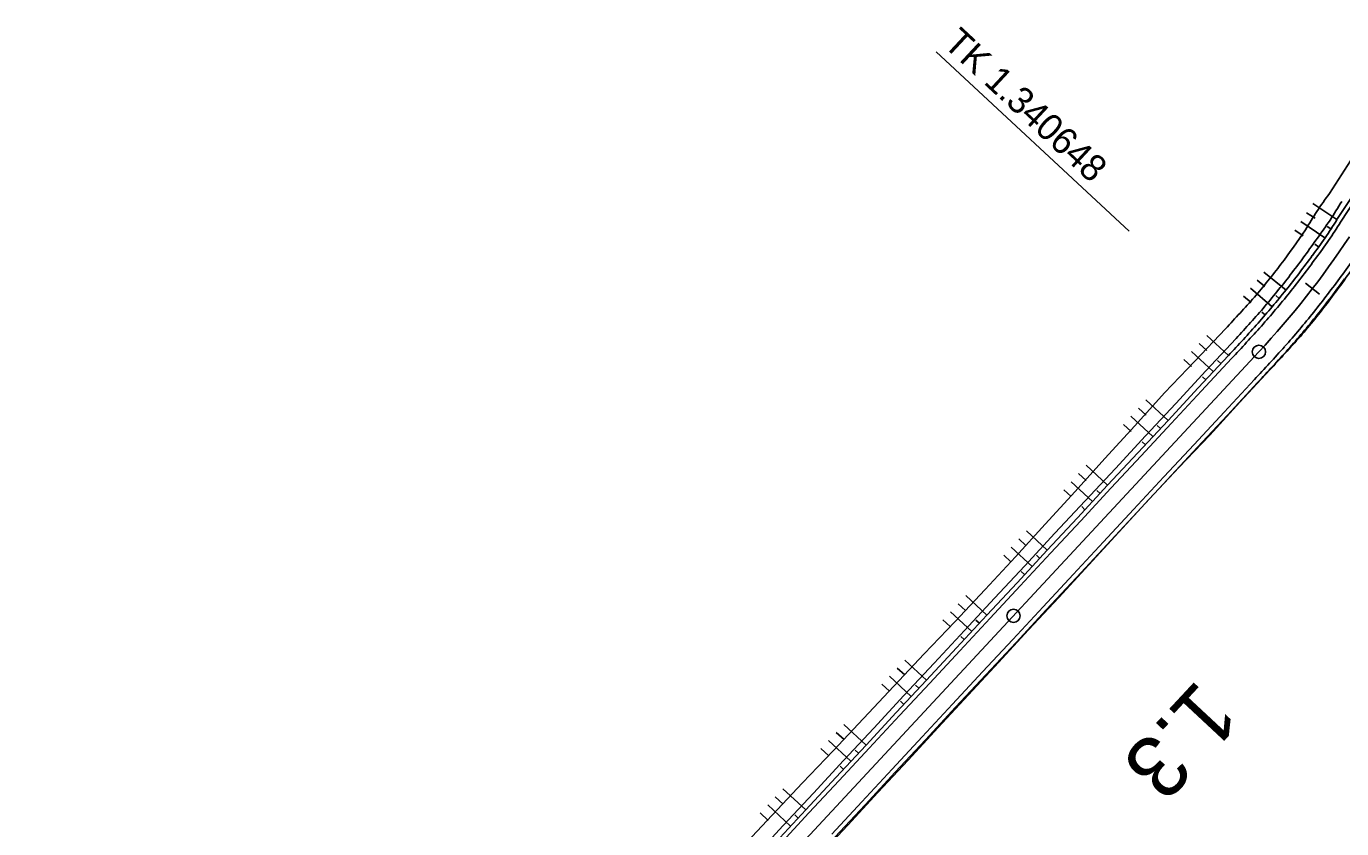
# Model space of a CAD drawing. Extents: x -481645 to -478728, y -1113199 to -1110710.
# Drawn here: x -479136.3 to -478987.9, y -1110857.1 to -1110766.6 of the extents above; entities that cross this region are included whole.
import ezdxf

# ---------------------------------------------------------------- set-up
doc = ezdxf.new("R2010")
doc.units = 0
for name, color, linetype in [('CP14_HATCH_SLOPE_L', 7, 'Continuous'), ('CP1_HECTOMETRY', 7, 'Continuous'), ('O6_HATCH_SLOPE_L', 7, 'Continuous'), ('O6_HATCH_SLOPE_R', 7, 'Continuous'), ('O6_HECTOMETRY', 7, 'Continuous'), ('O6_HLBODY', 7, 'Continuous'), ('O6_HRANA_TELESO', 7, 'Continuous'), ('O6_OSA', 7, 'Continuous'), ('O6_VOZOVKA', 7, 'Continuous'), ('O6_ZPEVKRAJ', 7, 'Continuous')]:
    doc.layers.add(name, color=color, linetype=linetype)

msp = doc.modelspace()

# ---------------------------------------------------------------- linework, layer by layer
at = {"layer": 'CP14_HATCH_SLOPE_L'}
for p, q in [((-478988.66, -1110796.55), (-478988.64, -1110796.57)), ((-478988.61, -1110796.59), (-478988.61, -1110796.59)), ((-478992.65, -1110801.54), (-478992.59, -1110801.59)), ((-478994.33, -1110803.47), (-478994.29, -1110803.5)), ((-478993.49, -1110802.51), (-478993.46, -1110802.53)), ((-478993.43, -1110802.55), (-478993.43, -1110802.55)), ((-478995.19, -1110804.41), (-478995.18, -1110804.43)), ((-478995.16, -1110804.44), (-478995.16, -1110804.44)), ((-478999.46, -1110809), (-478999.43, -1110809.02)), ((-479001.16, -1110810.83), (-479001.12, -1110810.87)), ((-479000.31, -1110809.92), (-479000.29, -1110809.93)), ((-479000.28, -1110809.95), (-479000.28, -1110809.95)), ((-479002.01, -1110811.75), (-479001.98, -1110811.77)), ((-479001.96, -1110811.79), (-479001.96, -1110811.79)), ((-479006.27, -1110816.32), (-479006.24, -1110816.35)), ((-479007.97, -1110818.15), (-479007.95, -1110818.17)), ((-479007.12, -1110817.24), (-479007.11, -1110817.25)), ((-479007.1, -1110817.26), (-479007.1, -1110817.26)), ((-479008.82, -1110819.07), (-479008.82, -1110819.07)), ((-479008.81, -1110819.08), (-479008.81, -1110819.08)), ((-479013.08, -1110823.65), (-479013.05, -1110823.67)), ((-479014.78, -1110825.48), (-479014.75, -1110825.51)), ((-479013.93, -1110824.56), (-479013.91, -1110824.57)), ((-479013.9, -1110824.59), (-479013.9, -1110824.59)), ((-479015.63, -1110826.39), (-479015.61, -1110826.41)), ((-479015.6, -1110826.43), (-479015.6, -1110826.43)), ((-479019.89, -1110830.97), (-479019.83, -1110831.02)), ((-479021.59, -1110832.8), (-479021.53, -1110832.86)), ((-479020.74, -1110831.89), (-479020.71, -1110831.91)), ((-479020.68, -1110831.94), (-479020.68, -1110831.94)), ((-479022.44, -1110833.72), (-479022.41, -1110833.75)), ((-479022.38, -1110833.77), (-479022.38, -1110833.77)), ((-479027.55, -1110839.21), (-479027.51, -1110839.24)), ((-479027.48, -1110839.27), (-479027.48, -1110839.27)), ((-479026.7, -1110838.29), (-479026.62, -1110838.36)), ((-479028.4, -1110840.12), (-479028.33, -1110840.19)), ((-479029.25, -1110841.04), (-479029.21, -1110841.07)), ((-479029.17, -1110841.11), (-479029.17, -1110841.11)), ((-479034.36, -1110846.53), (-479034.32, -1110846.57)), ((-479034.28, -1110846.61), (-479034.28, -1110846.61)), ((-479033.51, -1110845.62), (-479033.42, -1110845.69)), ((-479035.21, -1110847.45), (-479035.12, -1110847.52)), ((-479036.06, -1110848.36), (-479036.02, -1110848.4)), ((-479035.98, -1110848.44), (-479035.98, -1110848.44)), ((-479041.17, -1110853.85), (-479041.12, -1110853.9)), ((-479041.08, -1110853.94), (-479041.08, -1110853.94)), ((-479040.32, -1110852.94), (-479040.23, -1110853.02)), ((-479042.02, -1110854.77), (-479041.92, -1110854.85)), ((-479042.87, -1110855.69), (-479042.82, -1110855.73)), ((-479042.78, -1110855.77), (-479042.78, -1110855.77))]:
    msp.add_line(p, q, dxfattribs=at)
at = {"layer": 'CP1_HECTOMETRY'}
msp.add_line((-479231.87, -1111055.62), (-478997.26, -1110803.33), dxfattribs=at)
msp.add_arc((-479070.49, -1110735.23), 100, 317.0793, 326.545, dxfattribs=at)
at = {"layer": 'O6_HATCH_SLOPE_L'}
msp.add_circle((-479024.94, -1110833.1), 0.75, dxfattribs=at)
at = {"layer": 'O6_HATCH_SLOPE_R'}
for p, q in [((-478988.47, -1110788.42), (-478991.2, -1110786.61)), ((-478989.84, -1110790.47), (-478992.53, -1110788.62)), ((-478990.93, -1110788.27), (-478991.88, -1110787.64)), ((-478992.27, -1110790.25), (-478993.2, -1110789.6)), ((-478989.16, -1110789.46), (-478989.57, -1110789.18)), ((-478990.54, -1110791.47), (-478990.94, -1110791.19)), ((-478994.2, -1110796.36), (-478996.72, -1110794.34)), ((-478995.76, -1110798.24), (-478998.23, -1110796.16)), ((-478996.61, -1110795.96), (-478997.47, -1110795.26)), ((-478998.15, -1110797.78), (-478999, -1110797.05)), ((-478994.97, -1110797.3), (-478995.36, -1110796.99)), ((-478996.55, -1110799.17), (-478996.93, -1110798.84)), ((-479000.7, -1110803.73), (-479003.13, -1110801.48)), ((-479002.41, -1110805.56), (-479004.86, -1110803.28)), ((-479003.14, -1110803.17), (-479003.99, -1110802.38)), ((-479004.86, -1110804.99), (-479005.72, -1110804.19)), ((-479001.55, -1110804.65), (-479001.92, -1110804.3)), ((-479003.26, -1110806.48), (-479003.63, -1110806.14)), ((-479007.51, -1110811.06), (-479010, -1110808.74)), ((-479009.22, -1110812.89), (-479011.69, -1110810.59)), ((-479009.98, -1110810.47), (-479010.85, -1110809.67)), ((-479011.67, -1110812.31), (-479012.53, -1110811.51)), ((-479008.36, -1110811.97), (-479008.74, -1110811.63)), ((-479010.07, -1110813.8), (-479010.44, -1110813.46)), ((-479014.32, -1110818.38), (-479016.75, -1110816.12)), ((-479016.03, -1110820.21), (-479018.43, -1110817.97)), ((-479016.76, -1110817.82), (-479017.59, -1110817.05)), ((-479018.45, -1110819.66), (-479019.28, -1110818.89)), ((-479015.17, -1110819.29), (-479015.55, -1110818.95)), ((-479016.88, -1110821.13), (-479017.25, -1110820.78)), ((-479023.54, -1110825.17), (-479024.34, -1110824.43)), ((-479021.13, -1110825.7), (-479023.49, -1110823.51)), ((-479022.84, -1110827.53), (-479025.19, -1110825.35)), ((-479025.24, -1110827.01), (-479026.03, -1110826.27)), ((-479021.98, -1110826.62), (-479022.36, -1110826.27)), ((-479023.69, -1110828.45), (-479024.06, -1110828.1)), ((-479030.36, -1110832.48), (-479031.17, -1110831.73)), ((-479027.94, -1110833.02), (-479030.31, -1110830.82)), ((-479029.65, -1110834.86), (-479032.03, -1110832.64)), ((-479032.07, -1110834.3), (-479032.89, -1110833.54)), ((-479028.79, -1110833.94), (-479029.17, -1110833.59)), ((-479030.5, -1110835.77), (-479030.88, -1110835.42)), ((-479037.21, -1110839.77), (-479038.05, -1110838.99)), ((-479034.75, -1110840.35), (-479037.19, -1110838.08)), ((-479036.46, -1110842.18), (-479038.91, -1110839.9)), ((-479038.92, -1110841.59), (-479039.77, -1110840.8)), ((-479035.6, -1110841.26), (-479035.99, -1110840.91)), ((-479037.31, -1110843.09), (-479037.69, -1110842.74)), ((-479044.05, -1110847.06), (-479044.93, -1110846.25)), ((-479041.56, -1110847.67), (-479044.07, -1110845.34)), ((-479045.77, -1110848.88), (-479046.65, -1110848.06)), ((-479043.27, -1110849.5), (-479045.79, -1110847.16)), ((-479042.41, -1110848.59), (-479042.8, -1110848.23)), ((-479044.12, -1110850.42), (-479044.5, -1110850.06)), ((-479048.37, -1110854.99), (-479050.94, -1110852.6)), ((-479050.9, -1110854.35), (-479051.8, -1110853.51)), ((-479052.61, -1110856.17), (-479053.52, -1110855.32)), ((-479050.08, -1110856.82), (-479052.66, -1110854.42)), ((-479049.22, -1110855.91), (-479049.61, -1110855.55))]:
    msp.add_line(p, q, dxfattribs=at)
at = {"layer": 'O6_HECTOMETRY'}
msp.add_line((-479033.65, -1110769.49), (-479011.9, -1110789.71), dxfattribs=at)
msp.add_circle((-478997.26, -1110803.33), 0.75, dxfattribs=at)
at = {"layer": 'O6_HLBODY'}
msp.add_line((-478990.43, -1110796.81), (-478992.01, -1110795.59), dxfattribs=at)
at = {"layer": 'O6_HRANA_TELESO'}
for p, q in [((-479003.24, -1110805.48), (-478999.84, -1110801.82)), ((-479006.65, -1110809.14), (-479003.24, -1110805.48)), ((-479010.05, -1110812.8), (-479006.65, -1110809.14)), ((-479013.45, -1110816.47), (-479010.05, -1110812.8)), ((-479016.86, -1110820.13), (-479013.45, -1110816.47)), ((-479020.26, -1110823.79), (-479016.86, -1110820.13)), ((-479023.67, -1110827.45), (-479020.26, -1110823.79)), ((-479027.07, -1110831.11), (-479023.67, -1110827.45)), ((-479030.48, -1110834.77), (-479027.07, -1110831.11)), ((-479033.88, -1110838.44), (-479030.48, -1110834.77)), ((-479037.29, -1110842.1), (-479033.88, -1110838.44)), ((-479040.69, -1110845.76), (-479037.29, -1110842.1)), ((-479044.1, -1110849.42), (-479040.69, -1110845.76)), ((-479047.5, -1110853.08), (-479044.1, -1110849.42)), ((-479050.91, -1110856.74), (-479047.5, -1110853.08)), ((-479054.31, -1110860.41), (-479050.91, -1110856.74))]:
    msp.add_line(p, q, dxfattribs=at)
for centre, radius, start, end in [((-479029.62, -1110761.53), 48.54, 323.3654, 329.1948), ((-479070.49, -1110735.23), 97.08, 322.4379, 325.3027), ((-479070.49, -1110735.23), 97.08, 319.5731, 322.4379), ((-479215.19, -1110605.74), 291.25, 317.6812, 318.6398)]:
    msp.add_arc(centre, radius, start, end, dxfattribs=at)
at = {"layer": 'O6_OSA'}
for p, q in [((-478989.32, -1110785.48), (-478986.59, -1110781.28)), ((-479004.47, -1110804.34), (-479001.02, -1110800.72)), ((-479007.91, -1110807.97), (-479004.47, -1110804.34)), ((-478999.43, -1110809.02), (-478996.03, -1110805.36)), ((-479011.27, -1110811.67), (-479007.91, -1110807.97)), ((-479002.8, -1110812.72), (-478999.43, -1110809.02)), ((-479014.64, -1110815.37), (-479011.27, -1110811.67)), ((-479006.24, -1110816.35), (-479002.8, -1110812.72)), ((-479018, -1110819.06), (-479014.64, -1110815.37)), ((-479009.67, -1110819.99), (-479006.24, -1110816.35)), ((-479021.37, -1110822.76), (-479018, -1110819.06)), ((-479013.05, -1110823.67), (-479009.67, -1110819.99)), ((-479024.73, -1110826.46), (-479021.37, -1110822.76)), ((-479016.44, -1110827.34), (-479013.05, -1110823.67)), ((-479028.14, -1110830.12), (-479024.73, -1110826.46)), ((-479019.83, -1110831.02), (-479016.44, -1110827.34)), ((-479031.57, -1110833.76), (-479028.14, -1110830.12)), ((-479023.23, -1110834.69), (-479019.83, -1110831.02)), ((-479035, -1110837.4), (-479031.57, -1110833.76)), ((-479026.62, -1110838.36), (-479023.23, -1110834.69)), ((-479038.43, -1110841.03), (-479035, -1110837.4)), ((-479030.03, -1110842.02), (-479026.62, -1110838.36)), ((-479041.86, -1110844.67), (-479038.43, -1110841.03)), ((-479033.42, -1110845.69), (-479030.03, -1110842.02)), ((-479045.29, -1110848.31), (-479041.86, -1110844.67)), ((-479036.83, -1110849.36), (-479033.42, -1110845.69)), ((-479048.73, -1110851.94), (-479045.29, -1110848.31)), ((-479040.23, -1110853.02), (-479036.83, -1110849.36)), ((-479052.16, -1110855.58), (-479048.73, -1110851.94)), ((-479043.62, -1110856.69), (-479040.23, -1110853.02)), ((-479055.59, -1110859.22), (-479052.16, -1110855.58)), ((-479047.03, -1110860.35), (-479043.62, -1110856.69))]:
    msp.add_line(p, q, dxfattribs=at)
for centre, radius, start, end in [((-478950.8, -1110813.66), 47.73, 143.8045, 149.6908), ((-479070.97, -1110735.9), 95.48, 322.9287, 325.7936), ((-479070.67, -1110735.46), 95.51, 319.7497, 322.6145), ((-479070.67, -1110735.48), 102.31, 322.6103, 325.4751), ((-479210.78, -1110605.51), 286.54, 317.0581, 318.0186), ((-479070.62, -1110735.4), 102.33, 319.6909, 322.5557), ((-479220.96, -1110596.42), 307, 317.1107, 318.0626)]:
    msp.add_arc(centre, radius, start, end, dxfattribs=at)
at = {"layer": 'O6_VOZOVKA'}
for p, q in [((-478988.05, -1110788.7), (-478985.3, -1110784.53)), ((-479003.74, -1110807.74), (-479000.34, -1110804.07)), ((-479001.18, -1110810.12), (-478997.77, -1110806.46)), ((-479007.15, -1110811.4), (-479003.74, -1110807.74)), ((-479004.58, -1110813.78), (-479001.18, -1110810.12)), ((-479010.55, -1110815.06), (-479007.15, -1110811.4)), ((-479007.99, -1110817.44), (-479004.58, -1110813.78)), ((-479013.96, -1110818.72), (-479010.55, -1110815.06)), ((-479011.39, -1110821.1), (-479007.99, -1110817.44)), ((-479017.36, -1110822.38), (-479013.96, -1110818.72)), ((-479014.8, -1110824.77), (-479011.39, -1110821.1)), ((-479020.77, -1110826.04), (-479017.36, -1110822.38)), ((-479018.2, -1110828.43), (-479014.8, -1110824.77)), ((-479024.17, -1110829.7), (-479020.77, -1110826.04)), ((-479021.61, -1110832.09), (-479018.2, -1110828.43)), ((-479027.58, -1110833.37), (-479024.17, -1110829.7)), ((-479025.01, -1110835.75), (-479021.61, -1110832.09)), ((-479030.98, -1110837.03), (-479027.58, -1110833.37)), ((-479028.42, -1110839.41), (-479025.01, -1110835.75)), ((-479034.39, -1110840.69), (-479030.98, -1110837.03)), ((-479037.79, -1110844.35), (-479034.39, -1110840.69)), ((-479031.82, -1110843.07), (-479028.42, -1110839.41)), ((-479035.23, -1110846.73), (-479031.82, -1110843.07)), ((-479041.2, -1110848.01), (-479037.79, -1110844.35)), ((-479044.6, -1110851.67), (-479041.2, -1110848.01)), ((-479038.63, -1110850.4), (-479035.23, -1110846.73)), ((-479042.04, -1110854.06), (-479038.63, -1110850.4)), ((-479048.01, -1110855.33), (-479044.6, -1110851.67)), ((-479045.44, -1110857.72), (-479042.04, -1110854.06)), ((-479051.41, -1110859), (-479048.01, -1110855.33))]:
    msp.add_line(p, q, dxfattribs=at)
for centre, radius, start, end in [((-479029.91, -1110762.98), 49.12, 322.682, 328.4306), ((-479028.47, -1110763.97), 50.88, 322.693, 328.4079), ((-479070.49, -1110735.23), 98.25, 321.2966, 324.1614), ((-479070.49, -1110735.23), 101.75, 321.2966, 324.1614), ((-479070.49, -1110735.23), 98.25, 318.4318, 321.2966), ((-479070.49, -1110735.23), 101.75, 318.4318, 321.2966), ((-479215.6, -1110602.73), 294.75, 316.9136, 317.8775), ((-479220.76, -1110598), 305.25, 316.9283, 317.8746)]:
    msp.add_arc(centre, radius, start, end, dxfattribs=at)
at = {"layer": 'O6_ZPEVKRAJ'}
for p, q in [((-478988.47, -1110788.42), (-478985.71, -1110784.25)), ((-479004.11, -1110807.4), (-479000.7, -1110803.73)), ((-479007.51, -1110811.06), (-479004.11, -1110807.4)), ((-479000.81, -1110810.46), (-478997.41, -1110806.8)), ((-479010.92, -1110814.72), (-479007.51, -1110811.06)), ((-479004.22, -1110814.12), (-479000.81, -1110810.46)), ((-479014.32, -1110818.38), (-479010.92, -1110814.72)), ((-479007.62, -1110817.78), (-479004.22, -1110814.12)), ((-479017.73, -1110822.04), (-479014.32, -1110818.38)), ((-479011.03, -1110821.44), (-479007.62, -1110817.78)), ((-479014.43, -1110825.1), (-479011.03, -1110821.44)), ((-479021.13, -1110825.7), (-479017.73, -1110822.04)), ((-479024.54, -1110829.36), (-479021.13, -1110825.7)), ((-479017.84, -1110828.77), (-479014.43, -1110825.1)), ((-479021.24, -1110832.43), (-479017.84, -1110828.77)), ((-479027.94, -1110833.02), (-479024.54, -1110829.36)), ((-479031.35, -1110836.69), (-479027.94, -1110833.02)), ((-479024.65, -1110836.09), (-479021.24, -1110832.43)), ((-479028.05, -1110839.75), (-479024.65, -1110836.09)), ((-479034.75, -1110840.35), (-479031.35, -1110836.69)), ((-479038.16, -1110844.01), (-479034.75, -1110840.35)), ((-479031.46, -1110843.41), (-479028.05, -1110839.75)), ((-479034.86, -1110847.07), (-479031.46, -1110843.41)), ((-479041.56, -1110847.67), (-479038.16, -1110844.01)), ((-479044.97, -1110851.33), (-479041.56, -1110847.67)), ((-479038.27, -1110850.74), (-479034.86, -1110847.07)), ((-479041.67, -1110854.4), (-479038.27, -1110850.74)), ((-479048.37, -1110854.99), (-479044.97, -1110851.33)), ((-479051.78, -1110858.66), (-479048.37, -1110854.99)), ((-479045.08, -1110858.06), (-479041.67, -1110854.4))]:
    msp.add_line(p, q, dxfattribs=at)
for centre, radius, start, end in [((-479030.11, -1110762.84), 48.88, 322.6803, 328.434), ((-479070.49, -1110735.23), 97.75, 321.2966, 324.1614), ((-479070.49, -1110735.23), 102.25, 321.2966, 324.1614), ((-479070.49, -1110735.23), 97.75, 318.4318, 321.2966), ((-479070.49, -1110735.23), 102.25, 318.4318, 321.2966), ((-479214.86, -1110603.41), 293.25, 316.9114, 317.878), ((-479221.5, -1110597.32), 306.75, 316.9304, 317.8742)]:
    msp.add_arc(centre, radius, start, end, dxfattribs=at)

# ---------------------------------------------------------------- texts
at = {"layer": 'O6_HATCH_SLOPE_L'}
msp.add_text('1.3', height=7, rotation=227.0337, dxfattribs=at).set_placement((-479004.13, -1110840.1))
at = {"layer": 'O6_HECTOMETRY'}
msp.add_text('TK 1.340648', height=2.999, rotation=317.0793, dxfattribs=at).set_placement((-479032.97, -1110768.76))

doc.saveas('drawing.dxf')
